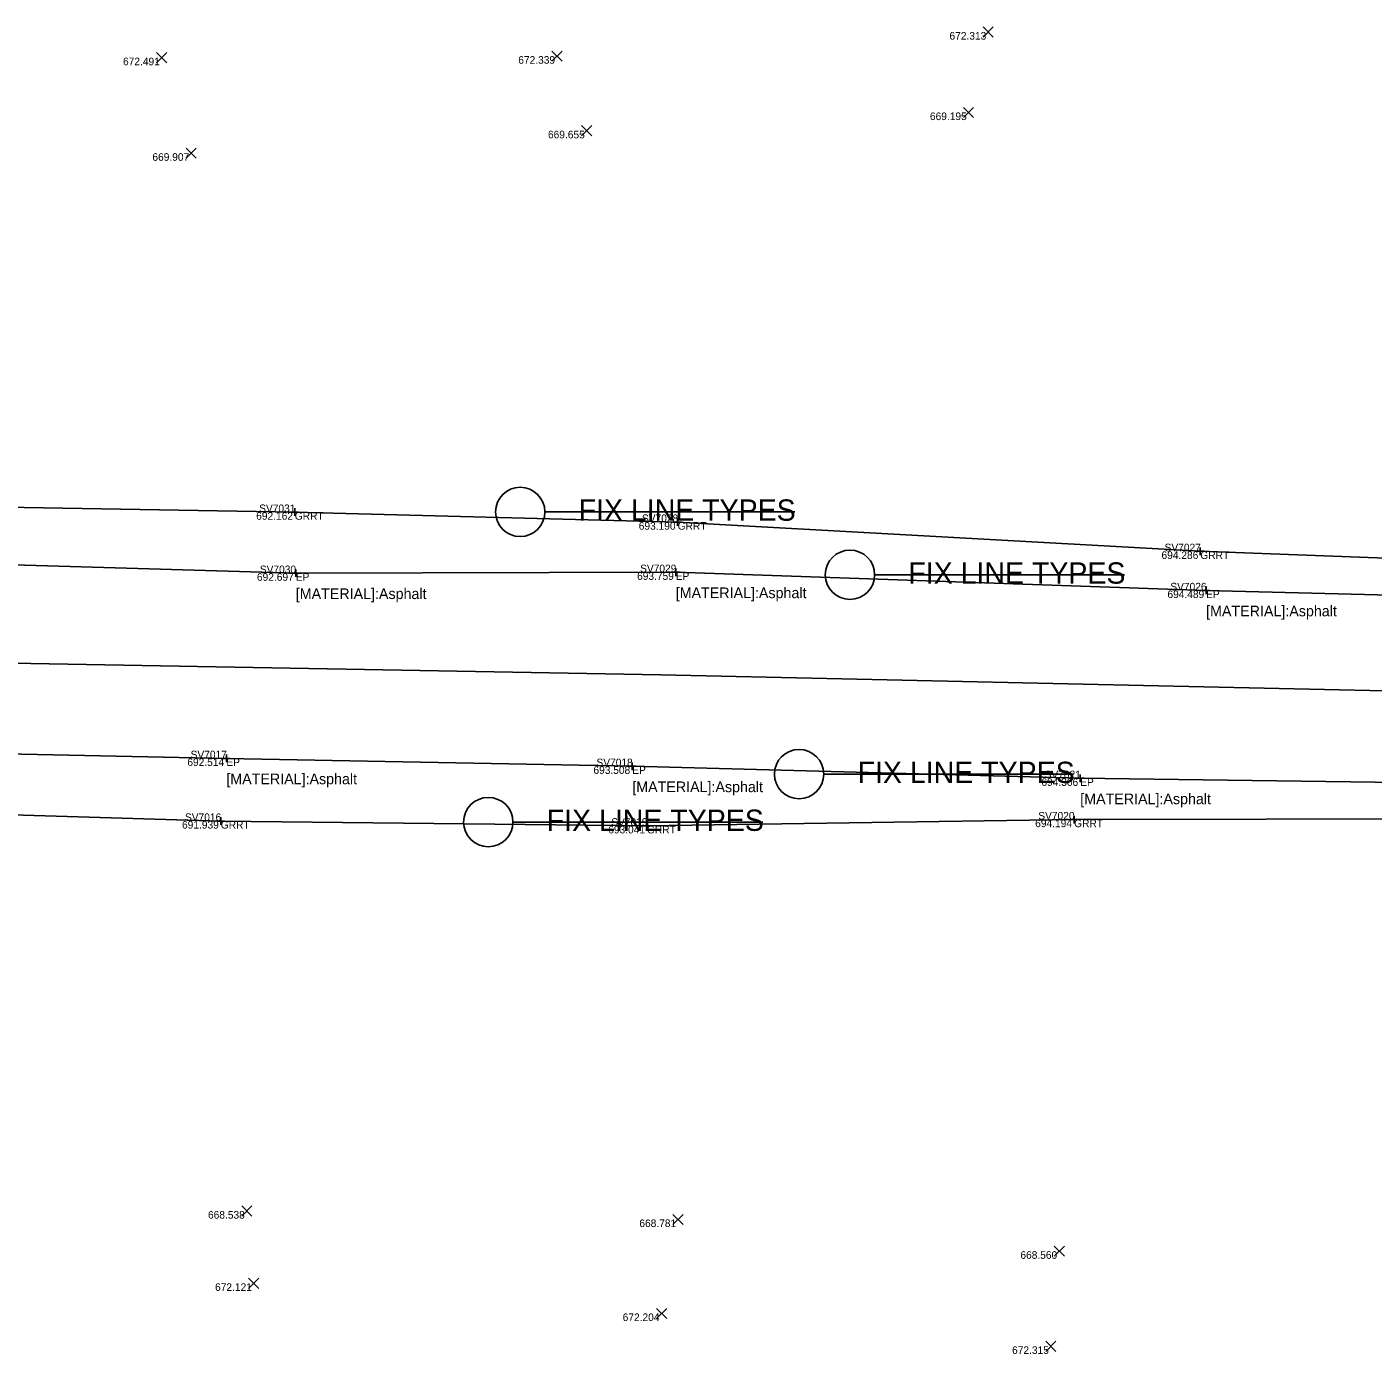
# Model space of a CAD drawing. Extents: x 1659932 to 1663108, y 619867 to 620611.
# Drawn here: x 1661002.1 to 1661178.9, y 620147.9 to 620322.2 of the extents above; entities that cross this region are included whole.
import ezdxf

# ---------------------------------------------------------------- set-up
doc = ezdxf.new("R2010")
doc.units = 0
for name, color, linetype in [('PM_X_CL_Dashed', 7, 'Continuous'), ('PV_X_EOP', 7, 'Continuous'), ('RD_X_GR_Rt', 7, 'Continuous'), ('SC_Scratch6', 7, 'Continuous'), ('SV_X_Random_Point', 7, 'Continuous'), ('SV_X_Shot_Marker', 7, 'Continuous'), ('SV_X_Text', 7, 'Continuous'), ('SV_X_Text_Comment', 7, 'Continuous'), ('SV_X_Text_Elevation', 7, 'Continuous'), ('SV_X_Text_Name', 7, 'Continuous')]:
    doc.layers.add(name, color=color, linetype=linetype)

msp = doc.modelspace()

# ---------------------------------------------------------------- linework, layer by layer
at = {"layer": 'PM_X_CL_Dashed'}
msp.add_lwpolyline([(1660473.33, 620249.8), (1660569.82, 620247.52), (1660683.17, 620245.58), (1660845.9, 620242.37), (1660966.03, 620239.29), (1661085.35, 620237.14), (1661180.4, 620235.01), (1661204.65, 620234.52)], dxfattribs=at)
at = {"layer": 'PV_X_EOP'}
for points in [[(1661208.92, 620246.9), (1661156.94, 620248.21), (1661087.29, 620250.6), (1661037.39, 620250.48), (1660981.01, 620252.16), (1660916.41, 620253.34), (1660855.2, 620254.44), (1660801.44, 620255.57), (1660749.64, 620256.49), (1660700.03, 620257.78), (1660643.44, 620258.64), (1660593.17, 620259.57)], [(1660597.37, 620234.1), (1660651.64, 620233.44), (1660703.42, 620232.61), (1660757.32, 620231.35), (1660809.76, 620230.12), (1660857.03, 620229.26), (1660910.07, 620228.44), (1660968.25, 620227.38), (1661028.27, 620226.15), (1661081.58, 620225.11), (1661140.41, 620223.53), (1661201.71, 620222.7)]]:
    msp.add_lwpolyline(points, dxfattribs=at)
at = {"layer": 'RD_X_GR_Rt'}
for points in [[(1661224.69, 620250.79), (1661156.18, 620253.35), (1661087.54, 620257.19), (1661037.26, 620258.5), (1660981.37, 620259.47), (1660918.68, 620260.81), (1660856.77, 620262.08), (1660800.7, 620262.74), (1660750.31, 620264.54), (1660700.27, 620265.16), (1660644.43, 620266.52), (1660592.86, 620267.53)], [(1660596.86, 620226.32), (1660650.68, 620225.81), (1660702.7, 620224.83), (1660759.05, 620223.97), (1660808.86, 620222.78), (1660856.77, 620221.69), (1660908.98, 620220.55), (1660971.26, 620219.59), (1661027.54, 620217.92), (1661083.51, 620217.29), (1661139.61, 620218.11), (1661215.13, 620218.24)]]:
    msp.add_lwpolyline(points, dxfattribs=at)
at = {"layer": 'SC_Scratch6'}
for p, q in [((1661070.1, 620258.53), (1661102.91, 620258.53)), ((1661113.41, 620250.27), (1661146.22, 620250.27)), ((1661106.74, 620224.08), (1661139.54, 620224.08)), ((1661065.92, 620217.78), (1661098.72, 620217.78))]:
    msp.add_line(p, q, dxfattribs=at)
for centre in [(1661066.86, 620258.53), (1661110.17, 620250.27), (1661103.49, 620224.08), (1661062.67, 620217.78)]:
    msp.add_circle(centre, 3.24, dxfattribs=at)
at = {"layer": 'SV_X_Random_Point'}
for p, q in [((1661127.64, 620320.91), (1661128.97, 620322.25)), ((1661127.64, 620322.25), (1661128.97, 620320.91)), ((1661019.12, 620317.54), (1661020.45, 620318.88)), ((1661019.12, 620318.88), (1661020.45, 620317.54)), ((1661071.03, 620317.75), (1661072.36, 620319.08)), ((1661071.03, 620319.08), (1661072.36, 620317.75)), ((1661125.07, 620310.34), (1661126.4, 620311.68)), ((1661125.07, 620311.68), (1661126.4, 620310.34)), ((1661074.92, 620307.94), (1661076.25, 620309.28)), ((1661074.92, 620309.28), (1661076.25, 620307.94)), ((1661022.99, 620304.99), (1661024.32, 620306.32)), ((1661022.99, 620306.32), (1661024.32, 620304.99)), ((1661030.29, 620166.02), (1661031.63, 620167.35)), ((1661030.29, 620167.35), (1661031.63, 620166.02)), ((1661086.92, 620164.9), (1661088.25, 620166.24)), ((1661086.92, 620166.24), (1661088.25, 620164.9)), ((1661137, 620160.73), (1661138.33, 620162.07)), ((1661137, 620162.07), (1661138.33, 620160.73)), ((1661031.2, 620156.51), (1661032.53, 620157.85)), ((1661031.2, 620157.85), (1661032.53, 620156.51)), ((1661084.78, 620152.55), (1661086.11, 620153.89)), ((1661084.78, 620153.89), (1661086.11, 620152.55)), ((1661135.87, 620148.23), (1661137.2, 620149.56)), ((1661135.87, 620149.56), (1661137.2, 620148.23))]:
    msp.add_line(p, q, dxfattribs=at)
at = {"layer": 'SV_X_Shot_Marker'}
for p, q in [((1661036.76, 620258.5), (1661037.76, 620258.5)), ((1661037.26, 620259), (1661037.26, 620258)), ((1661037.26, 620258.5), (1661037.26, 620258.5)), ((1661087.04, 620257.19), (1661088.04, 620257.19)), ((1661087.54, 620257.69), (1661087.54, 620256.69)), ((1661087.54, 620257.19), (1661087.54, 620257.19)), ((1661155.68, 620253.35), (1661156.68, 620253.35)), ((1661156.18, 620253.85), (1661156.18, 620252.85)), ((1661156.18, 620253.35), (1661156.18, 620253.35)), ((1661037.39, 620250.98), (1661037.39, 620249.98)), ((1661087.29, 620251.1), (1661087.29, 620250.1)), ((1661036.89, 620250.48), (1661037.89, 620250.48)), ((1661037.39, 620250.48), (1661037.39, 620250.48)), ((1661086.79, 620250.6), (1661087.79, 620250.6)), ((1661087.29, 620250.6), (1661087.29, 620250.6)), ((1661156.44, 620248.21), (1661157.44, 620248.21)), ((1661156.94, 620248.71), (1661156.94, 620247.71)), ((1661156.94, 620248.21), (1661156.94, 620248.21)), ((1661027.77, 620226.15), (1661028.77, 620226.15)), ((1661028.27, 620226.65), (1661028.27, 620225.65)), ((1661028.27, 620226.15), (1661028.27, 620226.15)), ((1661081.08, 620225.11), (1661082.08, 620225.11)), ((1661081.58, 620225.61), (1661081.58, 620224.61)), ((1661081.58, 620225.11), (1661081.58, 620225.11)), ((1661139.91, 620223.53), (1661140.91, 620223.53)), ((1661140.41, 620224.03), (1661140.41, 620223.03)), ((1661140.41, 620223.53), (1661140.41, 620223.53)), ((1661027.04, 620217.92), (1661028.04, 620217.92)), ((1661027.54, 620218.42), (1661027.54, 620217.42)), ((1661027.54, 620217.92), (1661027.54, 620217.92)), ((1661083.01, 620217.29), (1661084.01, 620217.29)), ((1661083.51, 620217.79), (1661083.51, 620216.79)), ((1661083.51, 620217.29), (1661083.51, 620217.29)), ((1661139.11, 620218.11), (1661140.11, 620218.11)), ((1661139.61, 620218.61), (1661139.61, 620217.61)), ((1661139.61, 620218.11), (1661139.61, 620218.11))]:
    msp.add_line(p, q, dxfattribs=at)

# ---------------------------------------------------------------- texts
at = {"layer": 'SC_Scratch6'}
for p in [(1661074.53, 620257.37), (1661117.84, 620249.1), (1661111.17, 620222.91), (1661070.35, 620216.62)]:
    msp.add_text('FIX LINE TYPES', height=2.8, dxfattribs=at).set_placement(p)
at = {"layer": 'SV_X_Text'}
for p in [(1661037.39, 620247.08), (1661087.29, 620247.2), (1661156.94, 620244.81), (1661028.27, 620222.75), (1661081.58, 620221.71), (1661140.41, 620220.13)]:
    msp.add_text('[MATERIAL]:Asphalt', height=1.4, dxfattribs=at).set_placement(p)
at = {"layer": 'SV_X_Text_Comment'}
for s, p in [('GRRT', (1661037.26, 620257.5)), ('GRRT', (1661087.54, 620256.19)), ('GRRT', (1661156.18, 620252.35)), ('EP', (1661037.39, 620249.48)), ('EP', (1661087.29, 620249.6)), ('EP', (1661156.94, 620247.21)), ('EP', (1661028.27, 620225.15)), ('EP', (1661081.58, 620224.11)), ('EP', (1661140.41, 620222.53)), ('GRRT', (1661027.54, 620216.92)), ('GRRT', (1661083.51, 620216.29)), ('GRRT', (1661139.61, 620217.11))]:
    msp.add_text(s, height=1, dxfattribs=at).set_placement(p)
at = {"layer": 'SV_X_Text_Elevation'}
for s, p in [('672.313', (1661123.24, 620320.58)), ('672.491', (1661014.7, 620317.21)), ('672.339', (1661066.61, 620317.41)), ('669.195', (1661120.67, 620310.01)), ('669.655', (1661070.51, 620307.61)), ('669.907', (1661018.56, 620304.66)), ('692.162', (1661032.19, 620257.5)), ('693.190', (1661082.43, 620256.19)), ('694.286', (1661151.08, 620252.35)), ('692.697', (1661032.29, 620249.48)), ('693.759', (1661082.21, 620249.6)), ('694.489', (1661151.86, 620247.21)), ('692.514', (1661023.15, 620225.15)), ('693.508', (1661076.48, 620224.11)), ('694.306', (1661135.31, 620222.53)), ('691.939', (1661022.45, 620216.92)), ('693.041', (1661078.42, 620216.29)), ('694.194', (1661134.49, 620217.11)), ('668.538', (1661025.86, 620165.68)), ('668.781', (1661082.51, 620164.57)), ('668.560', (1661132.55, 620160.4)), ('672.121', (1661026.79, 620156.18)), ('672.204', (1661080.32, 620152.22)), ('672.315', (1661131.46, 620147.9))]:
    msp.add_text(s, height=1, dxfattribs=at).set_placement(p)
at = {"layer": 'SV_X_Text_Name'}
for s, p in [('SV7031', (1661032.58, 620258.5)), ('SV7028', (1661082.85, 620257.19)), ('SV7027', (1661151.49, 620253.35)), ('SV7030', (1661032.67, 620250.48)), ('SV7029', (1661082.61, 620250.6)), ('SV7026', (1661152.24, 620248.21)), ('SV7017', (1661023.58, 620226.15)), ('SV7018', (1661076.88, 620225.11)), ('SV7021', (1661135.73, 620223.53)), ('SV7016', (1661022.84, 620217.92)), ('SV7020', (1661134.9, 620218.11)), ('SV7019', (1661078.82, 620217.29))]:
    msp.add_text(s, height=1, dxfattribs=at).set_placement(p)

doc.saveas('drawing.dxf')
